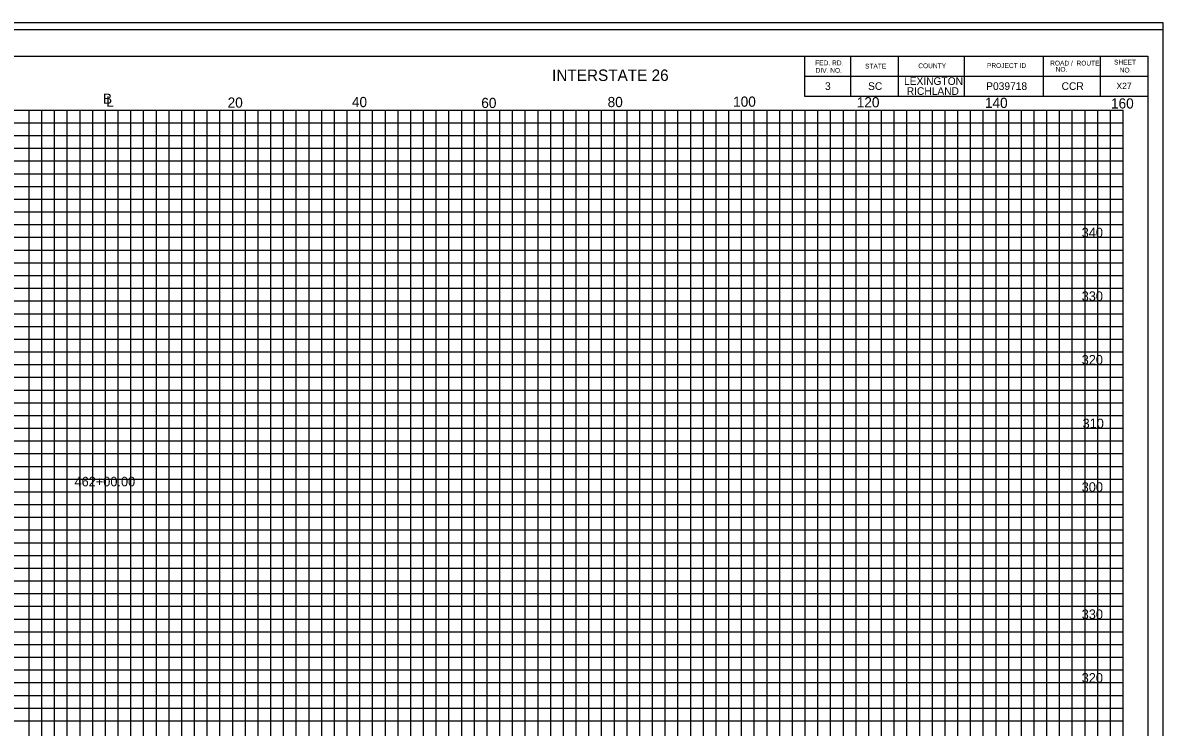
# Model space of a CAD drawing. Extents: x 967 to 1746, y 964 to 7904.
# Drawn here: x 1147 to 1326.3, y 7513 to 7623.7 of the extents above; entities that cross this region are included whole.
import ezdxf

# ---------------------------------------------------------------- set-up
doc = ezdxf.new("R2010")
doc.units = 0
for name, color, linetype in [('Default', 7, 'Continuous'), ('RD_SHT_Bndy', 7, 'Continuous'), ('RD_SHT_IplotShp', 7, 'Continuous'), ('RD_SHT_MjGrid', 7, 'Continuous'), ('RD_SHT_MnGrid', 7, 'Continuous'), ('RD_SHT_TX', 7, 'Continuous'), ('RD_Sketch1', 7, 'Continuous')]:
    doc.layers.add(name, color=color, linetype=linetype)

msp = doc.modelspace()

# ---------------------------------------------------------------- linework, layer by layer
at = {"layer": 'RD_SHT_Bndy'}
for p, q in [((996.11, 7618.46), (1323.89, 7618.46)), ((1269.89, 7618.46), (1269.89, 7612.21)), ((1277.14, 7618.46), (1277.14, 7612.21)), ((1284.64, 7618.46), (1284.64, 7612.21)), ((1295, 7618.46), (1295, 7612.21)), ((1307.43, 7618.46), (1307.43, 7612.21)), ((1316.39, 7618.46), (1316.39, 7612.21)), ((1323.89, 7618.46), (1323.89, 7408.98)), ((1269.89, 7615.33), (1323.89, 7615.33)), ((1269.89, 7612.21), (1323.89, 7612.21))]:
    msp.add_line(p, q, dxfattribs=at)
at = {"layer": 'RD_SHT_IplotShp'}
for points in [[(967.41, 7403.72), (1326.28, 7403.72), (1326.28, 7623.72), (967.41, 7623.72)], [(988.52, 7404.84), (1326.28, 7404.84), (1326.28, 7622.6), (988.52, 7622.6)]]:
    msp.add_lwpolyline(points, close=True, dxfattribs=at)
at = {"layer": 'RD_SHT_MjGrid'}
for p, q in [((1000, 7610), (1320, 7610)), ((1150, 7440), (1150, 7610)), ((1160, 7440), (1160, 7610)), ((1170, 7440), (1170, 7610)), ((1180, 7440), (1180, 7610)), ((1190, 7440), (1190, 7610)), ((1200, 7440), (1200, 7610)), ((1210, 7440), (1210, 7610)), ((1220, 7440), (1220, 7610)), ((1230, 7440), (1230, 7610)), ((1240, 7440), (1240, 7610)), ((1250, 7440), (1250, 7610)), ((1260, 7440), (1260, 7610)), ((1270, 7440), (1270, 7610)), ((1280, 7440), (1280, 7610)), ((1290, 7440), (1290, 7610)), ((1300, 7440), (1300, 7610)), ((1310, 7440), (1310, 7610)), ((1320, 7440), (1320, 7610)), ((1000, 7600), (1320, 7600)), ((1000, 7590), (1320, 7590)), ((1000, 7580), (1320, 7580)), ((1000, 7570), (1320, 7570)), ((1000, 7560), (1320, 7560)), ((1000, 7550), (1320, 7550)), ((1000, 7540), (1320, 7540)), ((1000, 7530), (1320, 7530)), ((1000, 7520), (1320, 7520))]:
    msp.add_line(p, q, dxfattribs=at)
at = {"layer": 'RD_SHT_MnGrid'}
for p, q in [((1148, 7440), (1148, 7610)), ((1152, 7440), (1152, 7610)), ((1154, 7440), (1154, 7610)), ((1156, 7440), (1156, 7610)), ((1158, 7440), (1158, 7610)), ((1162, 7440), (1162, 7610)), ((1164, 7440), (1164, 7610)), ((1166, 7440), (1166, 7610)), ((1168, 7440), (1168, 7610)), ((1172, 7440), (1172, 7610)), ((1174, 7440), (1174, 7610)), ((1176, 7440), (1176, 7610)), ((1178, 7440), (1178, 7610)), ((1182, 7440), (1182, 7610)), ((1184, 7440), (1184, 7610)), ((1186, 7440), (1186, 7610)), ((1188, 7440), (1188, 7610)), ((1192, 7440), (1192, 7610)), ((1194, 7440), (1194, 7610)), ((1196, 7440), (1196, 7610)), ((1198, 7440), (1198, 7610)), ((1202, 7440), (1202, 7610)), ((1204, 7440), (1204, 7610)), ((1206, 7440), (1206, 7610)), ((1208, 7440), (1208, 7610)), ((1212, 7440), (1212, 7610)), ((1214, 7440), (1214, 7610)), ((1216, 7440), (1216, 7610)), ((1218, 7440), (1218, 7610)), ((1222, 7440), (1222, 7610)), ((1224, 7440), (1224, 7610)), ((1226, 7440), (1226, 7610)), ((1228, 7440), (1228, 7610)), ((1232, 7440), (1232, 7610)), ((1234, 7440), (1234, 7610)), ((1236, 7440), (1236, 7610)), ((1238, 7440), (1238, 7610)), ((1242, 7440), (1242, 7610)), ((1244, 7440), (1244, 7610)), ((1246, 7440), (1246, 7610)), ((1248, 7440), (1248, 7610)), ((1252, 7440), (1252, 7610)), ((1254, 7440), (1254, 7610)), ((1256, 7440), (1256, 7610)), ((1258, 7440), (1258, 7610)), ((1262, 7440), (1262, 7610)), ((1264, 7440), (1264, 7610)), ((1266, 7440), (1266, 7610)), ((1268, 7440), (1268, 7610)), ((1272, 7440), (1272, 7610)), ((1274, 7440), (1274, 7610)), ((1276, 7440), (1276, 7610)), ((1278, 7440), (1278, 7610)), ((1282, 7440), (1282, 7610)), ((1284, 7440), (1284, 7610)), ((1286, 7440), (1286, 7610)), ((1288, 7440), (1288, 7610)), ((1292, 7440), (1292, 7610)), ((1294, 7440), (1294, 7610)), ((1296, 7440), (1296, 7610)), ((1298, 7440), (1298, 7610)), ((1302, 7440), (1302, 7610)), ((1304, 7440), (1304, 7610)), ((1306, 7440), (1306, 7610)), ((1308, 7440), (1308, 7610)), ((1312, 7440), (1312, 7610)), ((1314, 7440), (1314, 7610)), ((1316, 7440), (1316, 7610)), ((1318, 7440), (1318, 7610)), ((1000, 7608), (1320, 7608)), ((1000, 7606), (1320, 7606)), ((1000, 7604), (1320, 7604)), ((1000, 7602), (1320, 7602)), ((1000, 7598), (1320, 7598)), ((1000, 7596), (1320, 7596)), ((1000, 7594), (1320, 7594)), ((1000, 7592), (1320, 7592)), ((1000, 7588), (1320, 7588)), ((1000, 7586), (1320, 7586)), ((1000, 7584), (1320, 7584)), ((1000, 7582), (1320, 7582)), ((1000, 7578), (1320, 7578)), ((1000, 7576), (1320, 7576)), ((1000, 7574), (1320, 7574)), ((1000, 7572), (1320, 7572)), ((1000, 7568), (1320, 7568)), ((1000, 7566), (1320, 7566)), ((1000, 7564), (1320, 7564)), ((1000, 7562), (1320, 7562)), ((1000, 7558), (1320, 7558)), ((1000, 7556), (1320, 7556)), ((1000, 7554), (1320, 7554)), ((1000, 7552), (1320, 7552)), ((1000, 7548), (1320, 7548)), ((1000, 7546), (1320, 7546)), ((1000, 7544), (1320, 7544)), ((1000, 7542), (1320, 7542)), ((1000, 7538), (1320, 7538)), ((1000, 7536), (1320, 7536)), ((1000, 7534), (1320, 7534)), ((1000, 7532), (1320, 7532)), ((1000, 7528), (1320, 7528)), ((1000, 7526), (1320, 7526)), ((1000, 7524), (1320, 7524)), ((1000, 7522), (1320, 7522)), ((1000, 7518), (1320, 7518)), ((1000, 7516), (1320, 7516)), ((1000, 7514), (1320, 7514))]:
    msp.add_line(p, q, dxfattribs=at)
at = {"layer": 'RD_Sketch1'}
msp.add_lwpolyline([(967.41, 7403.72), (1326.28, 7403.72), (1326.28, 7623.72), (967.41, 7623.72)], close=True, dxfattribs=at)

# ---------------------------------------------------------------- texts
at = {"layer": 'Default'}
for s, height, p in [('X27', 1, (1318.94, 7613.3)), ('340', 1.5, (1313.47, 7590)), ('330', 1.5, (1313.47, 7580)), ('320', 1.5, (1313.47, 7570)), ('310', 1.5, (1313.61, 7560)), ('462+00.00', 1.5, (1155.13, 7550.86)), ('300', 1.5, (1313.47, 7550)), ('330', 1.5, (1313.47, 7530)), ('320', 1.5, (1313.47, 7520))]:
    msp.add_text(s, height=height, dxfattribs=at).set_placement(p)
at = {"layer": 'RD_SHT_TX'}
for s, height, p in [('ROAD /  ROUTE', 0.75, (1308.51, 7617.01)), ('SHEET', 0.75, (1318.56, 7617.16)), ('FED. RD.', 0.75, (1271.58, 7617.05)), ('DIV. NO.', 0.75, (1271.64, 7615.86)), ('STATE', 0.75, (1279.41, 7616.53)), ('COUNTY', 0.75, (1287.78, 7616.59)), ('PROJECT ID', 0.75, (1298.58, 7616.63)), ('   NO.', 0.75, (1308.51, 7616.03)), ('NO.', 0.75, (1319.45, 7615.91)), ('3', 1.2, (1273.12, 7613.17)), ('SC', 1.2, (1279.89, 7613.17)), ('LEXINGTON', 1.2, (1285.54, 7613.96)), ('P039718', 1.2, (1298.46, 7613.17)), ('CCR', 1.2, (1310.31, 7613.17)), ('B', 1.6, (1159.61, 7610.99)), ('RICHLAND', 1.2, (1285.97, 7612.39)), ('L', 1.6, (1160.12, 7610.54)), ('20', 1.6, (1179.2, 7610.38)), ('40', 1.6, (1198.74, 7610.47)), ('60', 1.6, (1219.08, 7610.33)), ('80', 1.6, (1238.94, 7610.47)), ('100', 1.6, (1258.67, 7610.53)), ('120', 1.6, (1278.11, 7610.43)), ('140', 1.6, (1298.26, 7610.34)), ('160', 1.6, (1318.08, 7610.25))]:
    msp.add_text(s, height=height, dxfattribs=at).set_placement(p)
msp.add_text('INTERSTATE 26', height=1.8, rotation=0, dxfattribs=at).set_placement((1230.21, 7614.58))

doc.saveas('drawing.dxf')
